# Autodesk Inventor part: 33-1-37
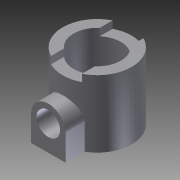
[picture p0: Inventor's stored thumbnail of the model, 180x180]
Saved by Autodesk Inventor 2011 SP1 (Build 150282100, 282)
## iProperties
Created: 2014-02
Part Number: 33-1-37
Document SubType Name: Modeling
Designer: Administrator
Density: 1 g/cm^3
Author: Administrator
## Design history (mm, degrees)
sketch "草图1"
  geometry: C1 r 19 at (0, 0); 1 further point
  constraints: 1 centre point, 1 coincident
  dimensions: "d0" = 38 diameter of C1
extrude "拉伸1" new body sketch "草图1" distance "d1" = 37; taper "d2" = 0 deg
sketch "草图2"
  geometry: L1 (-8.5, -19)-(8.5, -19); L2 (8.5, -19)-(8.5, 19); L3 (8.5, 19)-(-8.5, 19); L4 (-8.5, 19)-(-8.5, -19); C1 r 19 at (0, 0) reference; 2 further points
  constraints: 8 end point, 2 midpoint, 2 parallel, 1 horizontal, 1 horizontal alignment, 1 perpendicular, 1 vertical alignment
  dimensions: "d3" = 17 distance of L2.end L3.end; "d4" = 38 distance of L3.end L1.start
extrude "拉伸2" cut sketch "草图2" distance "d5" = 4; taper "d6" = 0 deg
hole "Hole1" diameter "d9" = 12; stored, may be unused: countersink angle "d13" = 90 deg, drill point angle "d15" = 0 deg; dims "d7" = 10, "d8" = 10, "d10" = 6, "d11" = 26, "d12" = 31, "d14" = 8
node "工作平面1"
sketch "草图3"
  geometry: L1 (-19, 0)-(19, 0) reference; L2 (9.5, 14)-(9.5, 0); L3 (-9.5, 14)-(-9.5, 0); A1 r 9.5 centre (0, 14) between (9.5, 14) and (-9.5, 14); 1 further point
  constraints: 4 end point, 2 point on circle, 2 point on line, 2 tangent, 1 centre point, 1 parallel, 1 perpendicular
  dimensions: "d17" = 19 diameter of A1; "d18" = 14 distance of point (0, 0) A1.centre
extrude "拉伸3" join sketch "草图3" stored distance "d19" = 4; taper "d20" = 0 deg
hole "Hole2" diameter "d23" = 13; stored, may be unused: countersink angle "d27" = 90 deg, drill point angle "d29" = 118 deg; dims "d21" = 10, "d22" = 10, "d24" = 6, "d25" = 26, "d26" = 31, "d28" = 17
node "实体1"
other parameters: "d16" = -27
